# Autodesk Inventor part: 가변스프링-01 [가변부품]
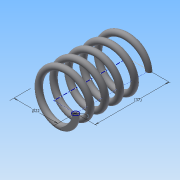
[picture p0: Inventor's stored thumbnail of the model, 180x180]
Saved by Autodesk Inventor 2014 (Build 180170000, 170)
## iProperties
Created: 2015-09
Part Number: 가변스프링-01 [가변부품]
Material: 강철, 탄소
Document SubType Name: Modeling
Designer: study
Density: 7.87 g/cm^3
Appearance: 반연마
Mass: 18.8817 g
Surface Area: 32.5359 cm^2
Volume: 2.3992 cm^3
Author: study
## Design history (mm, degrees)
sketch "스케치1"
  geometry: L1 (0, 0)-(11, 0); L2 (11, 0)-(11, 36.261); L3 (11, 36.261)-(0, 36.261); L4 (0, 36.261)-(0, 0); C1 r 1.5 at (11, 0)
  constraints: 8 end point, 2 parallel, 1 centre point, 1 coincident, 1 horizontal, 1 perpendicular
  dimensions: "d0" = 22 diameter of L2 L4; "d1" = 3 diameter of C1; "d2" = 36.2612 distance between parallel lines of L1 L3 (derived)
feature "코일1" sketch "스케치1" pitch "d3" = 10; turns "d5" = 5; dims "d4" = 36.2612 (= d2), "d6" = 0, angle "d7" = 90 deg, angle "d8" = 90 deg, "d9" = 0, "d10" = 0
node "작업 평면1"
sketch "스케치2"
  geometry: L1 (-12.5, 0)-(-9.5, 0) reference; 1 further point
  constraints: 1 horizontal alignment
extrude "돌출1" cut sketch "스케치2" distance "d12" = 10; taper "d13" = 0 deg
node "작업 평면2"
sketch "스케치3"
  geometry: L1 (-9.5, 0)-(-12.5, 0) reference; 1 further point
  constraints: 1 horizontal alignment
extrude "돌출2" cut sketch "스케치3" distance "d15" = 10; taper "d16" = 0 deg
node "솔리드1"
node "절단 모서리 투영1"
node "절단 모서리 투영2"
other parameters: "d11" = 0, "d14" = 36.2612 (= d2)
